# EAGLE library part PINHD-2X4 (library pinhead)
PIN HEADER
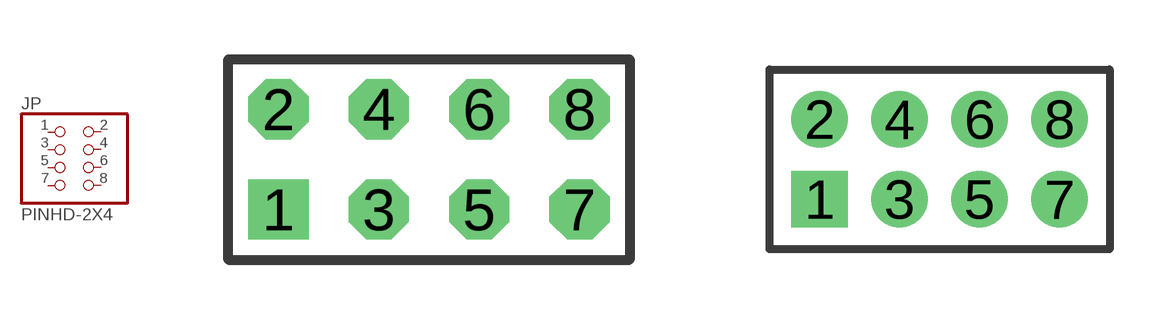
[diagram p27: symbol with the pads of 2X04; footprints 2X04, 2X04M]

Designator prefix JP

## PINHD-2X4  [2X04]
1  1  pas
2  2  pas
3  3  pas
4  4  pas
5  5  pas
6  6  pas
7  7  pas
8  8  pas

## PINHD-2X4M  [2X04M]
Pads as for 2X04

## Footprint 2X04 (pad centres in mm)
PIN HEADER - 0.1"
drill 1.016 square: 1 -3.81,-1.27
drill 1.016 octagon: 2 -3.81,1.27; 3 -1.27,-1.27; 4 -1.27,1.27; 5 1.27,-1.27; 6 1.27,1.27; 7 3.81,-1.27; 8 3.81,1.27

## Footprint 2X04M (pad centres in mm)
PIN HEADER - 2MM"
drill 0.914 square: 1 -3,-1
drill 0.914 round: 2 -3,1; 3 -1,-1; 4 -1,1; 5 1,-1; 6 1,1; 7 3,-1; 8 3,1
